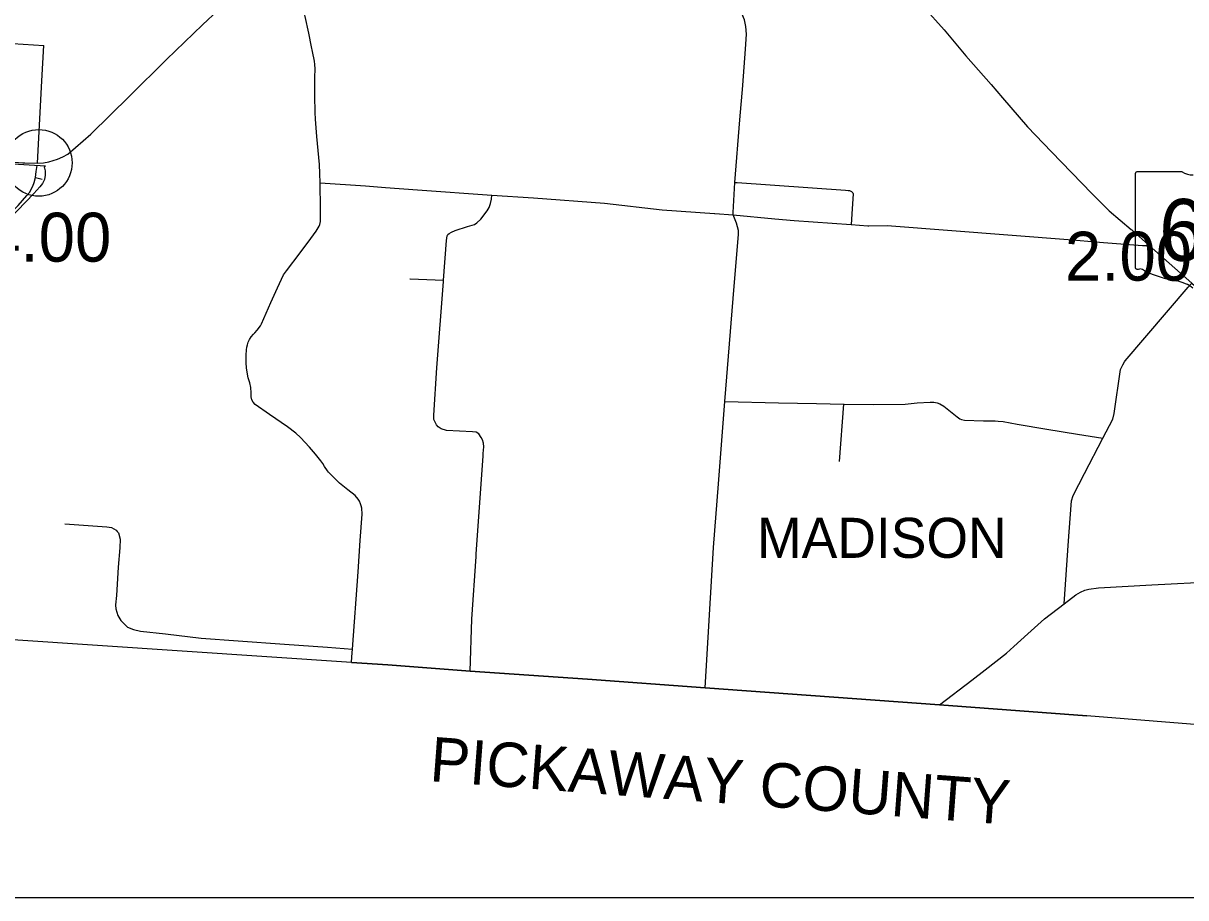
# Model space of a CAD drawing. Extents: x 1659811 to 1934326, y 644115 to 934867.
# Drawn here: x 1848780 to 1874937, y 650175 to 669837 of the extents above; entities that cross this region are included whole.
import ezdxf

# ---------------------------------------------------------------- set-up
doc = ezdxf.new("R2010")
doc.units = 0
for name, color, linetype in [('Default', 7, 'Continuous'), ('GM_X_Adjacent_County_Text', 7, 'Continuous'), ('GM_X_City_Street', 7, 'Continuous'), ('GM_X_Corporation', 7, 'Continuous'), ('GM_X_County', 7, 'Continuous'), ('GM_X_County_Road', 7, 'Continuous'), ('GM_X_State_Route', 7, 'Continuous'), ('GM_X_State_Shield', 7, 'Continuous'), ('GM_X_Township_Road', 7, 'Continuous'), ('GM_X_Township_Text', 7, 'Continuous'), ('SC_Scratch1', 7, 'Continuous')]:
    doc.layers.add(name, color=color, linetype=linetype)

msp = doc.modelspace()

# ---------------------------------------------------------------- linework, layer by layer
at = {"layer": 'Default'}
msp.add_circle((1849129, 666698), 750, dxfattribs=at)
at = {"layer": 'GM_X_City_Street'}
for points in [[(1847609, 669443), (1849242, 669337)], [(1849099, 666688), (1849197, 668542), (1849242, 669337)], [(1848969, 666119), (1848995, 666171), (1849029, 666256), (1849053, 666371), (1849069, 666502), (1849090, 666636)], [(1849053, 666371), (1849205, 666333)], [(1847754, 664925), (1847924, 665066), (1848036, 665165), (1848377, 665454), (1848662, 665739), (1848862, 665965), (1848928, 666037), (1848969, 666119)], [(1873723, 665190), (1874117, 664838), (1874566, 664446), (1875071, 663996), (1875446, 663673)], [(1872907, 664924), (1873089, 664908), (1873966, 664840), (1873995, 664841), (1874024, 664843), (1874064, 664841)], [(1874064, 664841), (1874117, 664838)], [(1873562, 662223), (1873575, 662245), (1874988, 663903), (1875071, 663996)]]:
    msp.add_lwpolyline(points, dxfattribs=at)
at = {"layer": 'GM_X_Corporation'}
msp.add_lwpolyline([(1847195, 666756), (1849281, 666631), (1849253, 666605), (1849260, 666581), (1849271, 666516), (1849274, 666421), (1849256, 666323), (1849213, 666237), (1849156, 666160), (1849019, 666011), (1848463, 665434)], dxfattribs=at)
at = {"layer": 'GM_X_County'}
msp.add_lwpolyline([(1877380, 653888), (1872712, 654264), (1869398, 654514), (1864124, 654894), (1861474, 655088), (1858836, 655268), (1856984, 655410), (1856164, 655463), (1848544, 655971), (1845619, 656217), (1840391, 656502), (1840376, 656506), (1835058, 656829), (1829957, 657174), (1828024, 657258), (1824608, 657476), (1824149, 657505)], dxfattribs=at)
at = {"layer": 'GM_X_County_Road'}
for points in [[(1864970, 668444), (1865034, 669256), (1865054, 669593), (1865039, 669765), (1865007, 669911), (1864949, 670055), (1864841, 670275), (1864704, 670513), (1864640, 670647), (1864594, 670775), (1864489, 671105)], [(1868274, 671000), (1868347, 670926), (1868610, 670653), (1869044, 670197), (1869498, 669689), (1869989, 669106), (1870557, 668457), (1870814, 668157), (1871379, 667510), (1871553, 667320), (1871913, 666946), (1872824, 666007), (1872995, 665840), (1873212, 665623), (1873465, 665411), (1873709, 665202), (1873723, 665190)], [(1855343, 668206), (1855343, 668329), (1855342, 668614), (1855345, 668809), (1855341, 668910), (1855330, 668988), (1855286, 669200), (1855262, 669308), (1855207, 669612), (1855120, 669991), (1855095, 670107), (1855089, 670185), (1855082, 670307)], [(1864756, 665581), (1864756, 665582), (1864793, 666258), (1864900, 667663), (1864970, 668440), (1864970, 668444)], [(1855462, 666252), (1855453, 666460), (1855444, 666664), (1855384, 667293), (1855359, 667683), (1855351, 667833), (1855343, 668206)], [(1853907, 661550), (1853904, 661622), (1853899, 661649), (1853876, 661750), (1853840, 661863), (1853806, 662080), (1853797, 662207), (1853798, 662372), (1853800, 662491), (1853809, 662551), (1853824, 662606), (1853844, 662666), (1853874, 662727), (1853911, 662789), (1853958, 662845), (1853993, 662875), (1854045, 662935), (1854117, 663031), (1854141, 663077), (1854242, 663315), (1854353, 663562), (1854498, 663888), (1854588, 664085), (1854636, 664182), (1854702, 664271), (1855010, 664676), (1855248, 664999), (1855370, 665164), (1855418, 665236), (1855436, 665272), (1855455, 665316), (1855465, 665381), (1855465, 665667), (1855462, 666252)], [(1855462, 666252), (1856483, 666179), (1856930, 666146), (1857651, 666095), (1859326, 665971), (1860259, 665910), (1861859, 665794), (1863158, 665640), (1864334, 665557)], [(1864334, 665557), (1864338, 665557), (1864754, 665527)], [(1864569, 661334), (1864755, 663649), (1864875, 665092), (1864872, 665174), (1864827, 665345), (1864754, 665527), (1864756, 665581)], [(1864754, 665527), (1865692, 665442), (1866128, 665403), (1867408, 665311), (1867785, 665280), (1867804, 665280)], [(1867804, 665280), (1868217, 665290), (1872391, 664968), (1872907, 664924)], [(1872662, 659716), (1873068, 660509), (1873300, 660936), (1873325, 661064), (1873471, 662054), (1873523, 662158), (1873562, 662223)], [(1856164, 655463), (1856176, 655593), (1856187, 655765), (1856312, 657499), (1856361, 658208), (1856403, 658797), (1856396, 658931), (1856383, 658986), (1856370, 659032), (1856344, 659088), (1856313, 659140), (1856245, 659220), (1856085, 659350), (1855892, 659499), (1855806, 659583), (1855651, 659742), (1855627, 659771), (1855555, 659874), (1855517, 659937), (1855473, 659999), (1855354, 660151), (1855218, 660305), (1855021, 660524), (1854916, 660624), (1854729, 660761), (1854321, 661040), (1853995, 661268), (1853951, 661320), (1853925, 661369), (1853910, 661437), (1853907, 661550)], [(1864124, 654894), (1864310, 658049), (1864422, 659478), (1864569, 661334)], [(1872302, 658199), (1872358, 659001), (1872365, 659097), (1872407, 659218), (1872662, 659716)], [(1869398, 654514), (1870125, 655063), (1870427, 655297), (1870901, 655676), (1871071, 655826), (1871383, 656105), (1871761, 656444), (1872202, 656780), (1872302, 658199)], [(1872202, 656780), (1872465, 656982), (1872570, 657045), (1872667, 657091), (1872757, 657116), (1872975, 657143), (1874171, 657208), (1875618, 657288), (1877649, 657393)], [(1856164, 655463), (1856984, 655410), (1857372, 655380)], [(1857372, 655380), (1858836, 655268), (1861474, 655088), (1864124, 654894), (1869398, 654514)]]:
    msp.add_lwpolyline(points, dxfattribs=at)
at = {"layer": 'GM_X_State_Route'}
for points in [[(1848819, 666696), (1849099, 666688), (1849232, 666701), (1849354, 666722), (1849455, 666750), (1849554, 666780), (1849673, 666832), (1849786, 666895), (1850303, 667340), (1851168, 668195), (1852000, 669022), (1852811, 669805), (1853162, 670133), (1853612, 670573), (1854310, 671256), (1854583, 671527)], [(1847311, 666801), (1848096, 666749), (1848769, 666698), (1848819, 666696)]]:
    msp.add_lwpolyline(points, dxfattribs=at)
at = {"layer": 'GM_X_State_Shield'}
for p, q in [((1874856, 666494), (1873836, 666494)), ((1873802, 666458), (1873802, 664345))]:
    msp.add_line(p, q, dxfattribs=at)
for centre, major_axis, start_param, end_param in [((1873842, 666462), (40.3, 0), 1.712693, 3.28349), ((1875098, 666740), (391, 0), 4.042523, 4.731795), ((1873842, 664340), (40.7, 0), 3.00124, 4.508301), ((1873849, 664556), (310, 0), 4.665946, 4.897461), ((1873912, 664223), (112, 0), 0.519207, 1.627899), ((1875325, 666121), (2665, 0), 4.195997, 4.488961), ((1874531, 663395), (834, 0), 0.823519, 1.323587)]:
    msp.add_ellipse(centre, major_axis=major_axis, ratio=0.8, start_param=start_param, end_param=end_param, dxfattribs=at)
at = {"layer": 'GM_X_Township_Road'}
for points in [[(1864793, 666258), (1864845, 666255)], [(1864845, 666255), (1867282, 666082), (1867340, 666075), (1867372, 666075), (1867416, 666052), (1867449, 666025), (1867457, 666003), (1867434, 665667), (1867408, 665311)], [(1859131, 660161), (1859141, 660315), (1859136, 660397), (1859113, 660471), (1859087, 660526), (1859032, 660604), (1858972, 660643), (1858892, 660654), (1858303, 660680), (1858187, 660721), (1858119, 660762), (1858080, 660806), (1858046, 660868), (1858022, 660927), (1858015, 661025), (1858084, 662089), (1858235, 664034), (1858237, 664062), (1858303, 664955), (1858319, 665061), (1858333, 665087), (1858364, 665113), (1858415, 665141), (1858502, 665176), (1858778, 665267), (1858933, 665312), (1858984, 665351), (1859074, 665434), (1859216, 665618), (1859264, 665696), (1859296, 665783), (1859319, 665883), (1859326, 665971)], [(1857478, 664093), (1857486, 664092), (1858237, 664062)], [(1864569, 661334), (1865771, 661306), (1866628, 661287), (1867244, 661275), (1867254, 661275), (1867914, 661265), (1868625, 661276), (1868895, 661302), (1869189, 661319), (1869267, 661318), (1869343, 661305), (1869405, 661280), (1869496, 661226), (1869796, 660991), (1869852, 660945), (1869893, 660924), (1869961, 660915), (1870383, 660898), (1870647, 660894), (1870717, 660887), (1870831, 660879), (1871146, 660826), (1871808, 660712), (1872499, 660597), (1873068, 660509)], [(1867144, 659985), (1867244, 661275)], [(1858973, 657900), (1859127, 660110), (1859131, 660161)], [(1849712, 658581), (1850657, 658512), (1850763, 658497), (1850869, 658438), (1850892, 658413), (1850926, 658377), (1850963, 658239), (1850950, 658044), (1850918, 657610), (1850875, 656971), (1850858, 656761), (1850858, 656754)], [(1858836, 655268), (1858871, 656441), (1858969, 657849), (1858973, 657900)], [(1850858, 656754), (1850857, 656750), (1850863, 656668), (1850906, 656518), (1850979, 656409), (1851122, 656261), (1851262, 656206), (1851416, 656169), (1851980, 656111), (1852783, 656012), (1853619, 655950), (1854656, 655877), (1855625, 655810), (1856187, 655765)], [(1869398, 654514), (1872712, 654264)]]:
    msp.add_lwpolyline(points, dxfattribs=at)
at = {"layer": 'SC_Scratch1'}
msp.add_lwpolyline([(1730291, 784675), (1926541, 784675), (1926541, 650175), (1730291, 650175)], close=True, dxfattribs=at)

# ---------------------------------------------------------------- texts
at = {"layer": 'Default'}
for s, p in [('4.00', (1847899, 664477)), ('2.00', (1872218, 664050))]:
    msp.add_text(s, height=1100, dxfattribs=at).set_placement(p)
at = {"layer": 'GM_X_Adjacent_County_Text'}
msp.add_text('PICKAWAY COUNTY', height=1000, rotation=355.6868, dxfattribs=at).set_placement((1857908, 652798))
at = {"layer": 'GM_X_State_Shield'}
msp.add_text('674', height=1392.2, dxfattribs=at).set_placement((1874334, 664494))
at = {"layer": 'GM_X_Township_Text'}
msp.add_text('MADISON', height=900, rotation=0, dxfattribs=at).set_placement((1865291, 657817))

doc.saveas('drawing.dxf')
